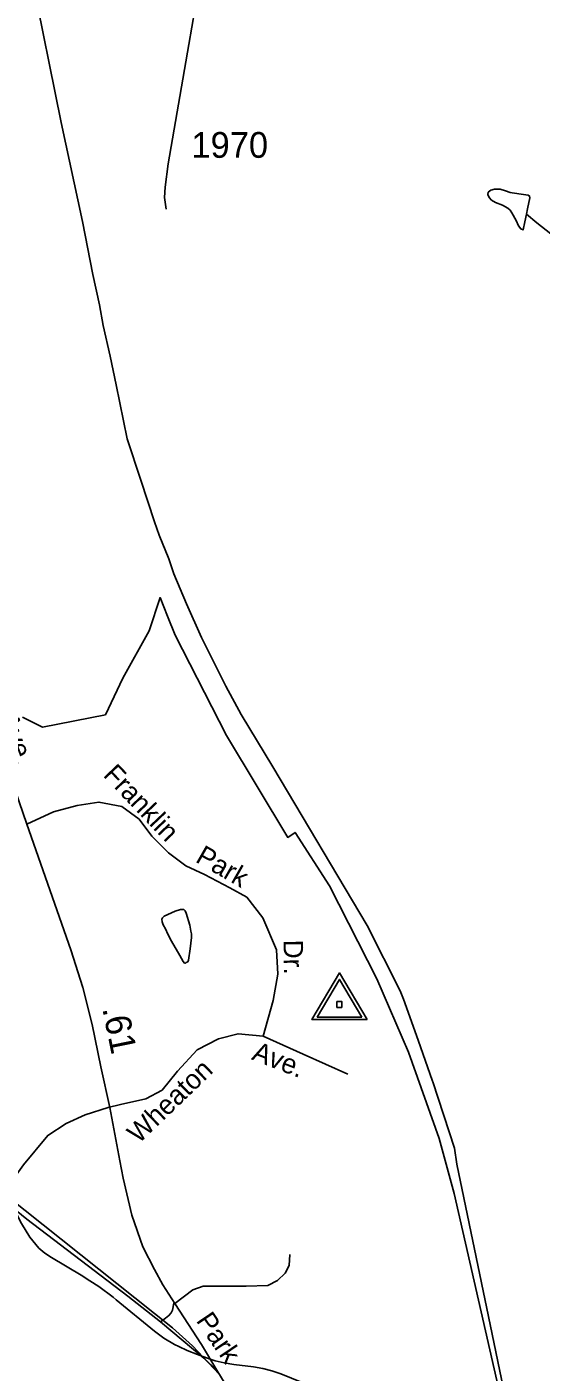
# Model space of a CAD drawing. Extents: x 2126262 to 2293712, y 749403 to 919119.
# Drawn here: x 2151844 to 2154336, y 831196 to 837718 of the extents above; entities that cross this region are included whole.
import ezdxf

# ---------------------------------------------------------------- set-up
doc = ezdxf.new("R2010")
doc.units = 0
for name, color, linetype in [('Exist Boundary Political City Limit New', 7, 'Continuous'), ('Exist Hydrographic Misc Water Feature', 7, 'Continuous'), ('Exist Railroad Mainline', 7, 'Continuous'), ('Exist Road Non-System Type 51', 7, 'Continuous'), ('Exist Road Non-System Type 51 Label', 7, 'Continuous'), ('Exist Road Primary NC Attributed', 7, 'Continuous'), ('Exist Road Primary US Attributed', 7, 'Continuous'), ('Exist Road Primary US Label', 7, 'Continuous'), ('Exist Road Primary US Mileage Hundredths English Label', 7, 'Continuous'), ('Exist Road Primary US Ramp 1 Lane  Attributed', 7, 'Continuous'), ('Exist Road Secondary Type 51 Attributed', 7, 'Continuous'), ('Exist Road Secondary Type 51 Number Label', 7, 'Continuous'), ('Exist Survey Geodetic Marker CELL', 7, 'Continuous'), ('Map Preparation Boundary City Limit Buffer Line', 7, 'Continuous')]:
    doc.layers.add(name, color=color, linetype=linetype)

msp = doc.modelspace()

# ---------------------------------------------------------------- linework, layer by layer
at = {"layer": 'Exist Boundary Political City Limit New'}
for points in [[(2151822.8, 834371.1), (2151919.2, 834322.9), (2152224.5, 834383.1), (2152308.2, 834559.9), (2152437.2, 834789), (2152489, 834950.8), (2152525.5, 834861.3), (2152561.8, 834768.9)], [(2152561.8, 834768.9), (2152810.8, 834282.7), (2153108, 833788.4), (2153144, 833812.6), (2153310, 833552.9), (2153539.5, 833102.3), (2153692.8, 832746.4), (2153843, 832328.9), (2153914.5, 832061.1), (2154336.2, 830213.6)], [(2152776.5, 831185.2), (2152645.8, 831322.7), (2152549, 831410.6), (2151294.2, 832408.8)]]:
    msp.add_lwpolyline(points, dxfattribs=at)
at = {"layer": 'Exist Hydrographic Misc Water Feature'}
for p, q in [((2152261.5, 831558.7), (2152277.3, 831546.8)), ((2152488.1, 831374.8), (2152507.6, 831360.7))]:
    msp.add_line(p, q, dxfattribs=at)
for points in [[(2154264.9, 836809.6), (2154257.1, 836773.5), (2154249.3, 836733.5), (2154237.4, 836739.4), (2154227.4, 836753.3), (2154215.1, 836779.3), (2154194.8, 836817.1), (2154186.8, 836829.1), (2154174.9, 836839), (2154148.8, 836852.9), (2154114.6, 836866.7), (2154096.5, 836878.6), (2154084.6, 836890.6), (2154078.5, 836904.5), (2154080.3, 836916.5), (2154092.2, 836926.5), (2154110.3, 836930.6), (2154138.4, 836930.8), (2154164.4, 836922.9), (2154186.3, 836915.1), (2154196.4, 836913.2), (2154250.3, 836905.5), (2154274.3, 836901.6), (2154280.3, 836897.6), (2154282.5, 836889.7), (2154270.8, 836835.6), (2154264.9, 836809.6)], [(2154264.9, 836809.6), (2154315.1, 836767.8), (2154383.4, 836714.2)], [(2152545.3, 833284.7), (2152585.5, 833214.9), (2152601.7, 833187.1), (2152607.9, 833179.1), (2152611.8, 833179.1), (2152615.9, 833181.1), (2152623.9, 833185.2), (2152627.7, 833193.2), (2152635.5, 833247.2), (2152641.1, 833303.3), (2152641.1, 833321.3), (2152639, 833333.2), (2152632.9, 833363.2), (2152616.5, 833421.1), (2152610.3, 833433), (2152604.4, 833439), (2152598.2, 833439), (2152588.4, 833438.9), (2152562.5, 833430.8), (2152508.6, 833406.5), (2152500.6, 833398.4), (2152498.6, 833392.4), (2152498.8, 833378.4), (2152504.7, 833364.4), (2152515, 833344.5), (2152527.1, 833318.5), (2152545.3, 833284.7)], [(2151793.6, 831962.8), (2151818.2, 831916.2), (2151858.4, 831850.8), (2151901, 831796.9), (2151930.2, 831772.2), (2151962.4, 831751.2), (2152106.3, 831666.2), (2152149, 831638.9)], [(2151793.6, 831962.8), (2151818.2, 831916.2), (2151858.4, 831850.8), (2151901, 831796.9), (2151930.2, 831772.2), (2151962.4, 831751.2), (2152106.3, 831666.2), (2152149, 831638.9)], [(2152149, 831638.9), (2152192.2, 831611.2), (2152261.5, 831558.7)], [(2152149, 831638.9), (2152192.2, 831611.2), (2152261.5, 831558.7)], [(2152277.3, 831546.8), (2152462.5, 831393.5), (2152488.1, 831374.8)], [(2152277.3, 831546.8), (2152462.5, 831393.5), (2152488.1, 831374.8)], [(2152507.6, 831360.7), (2152559.5, 831330.2), (2152580.4, 831320.3)], [(2152507.6, 831360.7), (2152559.5, 831330.2), (2152580.4, 831320.3)], [(2152580.4, 831320.3), (2152621.4, 831300.9), (2152671.2, 831280.5), (2152714.3, 831264.2), (2152737.2, 831257.1)], [(2152580.4, 831320.3), (2152621.4, 831300.9), (2152671.2, 831280.5), (2152714.3, 831264.2), (2152737.2, 831257.1)], [(2152737.2, 831257.1), (2152756.3, 831251.2), (2152799.6, 831241.1), (2152846.3, 831233.2)], [(2152737.2, 831257.1), (2152756.3, 831251.2), (2152799.6, 831241.1), (2152846.3, 831233.2)], [(2152846.3, 831233.2), (2152942.3, 831220.6), (2152987.4, 831213.1), (2153031.3, 831201.9)], [(2152846.3, 831233.2), (2152942.3, 831220.6), (2152987.4, 831213.1), (2153031.3, 831201.9)], [(2153031.3, 831201.9), (2153075.4, 831187.4), (2153177.5, 831144.9), (2153290.3, 831101.4), (2153311, 831088.2)], [(2153031.3, 831201.9), (2153075.4, 831187.4), (2153177.5, 831144.9), (2153290.3, 831101.4), (2153311, 831088.2)]]:
    msp.add_lwpolyline(points, dxfattribs=at)
at = {"layer": 'Exist Railroad Mainline'}
for points in [[(2151866.8, 837966.9), (2152010.1, 837254.7), (2152112.9, 836774.2), (2152163.3, 836518.2), (2152195.8, 836370.2), (2152213.7, 836270.6), (2152248.2, 836121.3), (2152276.2, 835982.2), (2152330.3, 835719.9), (2152395.6, 835520.9), (2152462.6, 835318.5), (2152485.6, 835254), (2152532, 835138.5), (2152556.1, 835065.8), (2152617.3, 834920.2), (2152689.5, 834756.9), (2152807.5, 834520.7), (2152882.8, 834384.8), (2153035.7, 834130.8), (2153493.6, 833360.6), (2153493.6, 833360.6), (2153652.7, 833045.1), (2153669.2, 833003.4), (2153740.5, 832804.5), (2153809.6, 832605.7), (2153811.5, 832603.7)], [(2153811.5, 832603.7), (2153916.7, 832281.3), (2153928.1, 832203.5), (2154081.3, 831464.6), (2155457.3, 824828.4), (2155457.3, 824828.4), (2155482, 824689.4), (2155494.5, 824619), (2155492.8, 824605), (2155538.8, 824353.7), (2155547.3, 824199.9)]]:
    msp.add_lwpolyline(points, dxfattribs=at)
at = {"layer": 'Exist Road Non-System Type 51'}
for points in [[(2151843.9, 833852.8), (2151972.4, 833912.2), (2152086.8, 833942.9), (2152192.8, 833959.7), (2152304.4, 833937.3), (2152388.2, 833875.9), (2152449.5, 833794.9), (2152529.7, 833713.8), (2152613.4, 833649.6), (2152705.4, 833607.7), (2152828.2, 833543.5), (2152909.1, 833498.8), (2152987.3, 833398.3), (2153054, 833243.2), (2153059.6, 833125.9), (2153037.2, 832997.4), (2152989.8, 832824.3)], [(2152989.8, 832824.3), (2152867.1, 832836.1), (2152772.2, 832811), (2152669, 832757.9), (2152574.1, 832654.6), (2152498.8, 832562.4), (2152420.6, 832520.6), (2152297.9, 832492.6), (2152237.8, 832478.4)], [(2152989.8, 832824.3), (2153182.3, 832737.7), (2153400, 832640)], [(2151713.3, 832041.6), (2151827.7, 832200.8), (2151944.9, 832343.2), (2152034.2, 832401.9), (2152126.3, 832443.8), (2152237.8, 832478.4)], [(2152560.2, 831528.3), (2152648.7, 831595), (2152698.9, 831613.1), (2152786.8, 831611.7), (2152906.8, 831611.7), (2153011.4, 831615.9), (2153058.1, 831640.4), (2153095.8, 831675.3), (2153115.3, 831713), (2153118.1, 831766)]]:
    msp.add_lwpolyline(points, dxfattribs=at)
at = {"layer": 'Exist Road Primary NC Attributed'}
for points in [[(2152491.9, 831440.3), (2152332.7, 831563.5), (2151843.7, 831937), (2151713.3, 832041.6), (2151403.6, 832265.4), (2151169.5, 832444.5)], [(2152764.3, 831205.6), (2152700.9, 831263.6), (2152491.9, 831440.3)]]:
    msp.add_lwpolyline(points, dxfattribs=at)
at = {"layer": 'Exist Road Primary US Attributed'}
for points in [[(2152560.2, 831528.3), (2152502.2, 831619.6), (2152461.9, 831693), (2152406.5, 831802.7), (2152353.1, 831955.9), (2152310.4, 832136.5), (2152294.4, 832220.8), (2152246.2, 832478.6), (2152202.5, 832675.8), (2152160.7, 832881.3), (2152114.8, 833060.6), (2152056.7, 833243.1), (2151843.9, 833852.8), (2151732.4, 834177.3)], [(2152764.3, 831205.6), (2152689.7, 831330), (2152560.2, 831528.3)], [(2153889.5, 829414), (2153865.8, 829525.7), (2153831, 829603.9), (2153751.5, 829717.9), (2153600.8, 829902.3), (2153432.1, 830154.3), (2153301.6, 830364.4), (2152899, 830985.6), (2152764.3, 831205.6)]]:
    msp.add_lwpolyline(points, dxfattribs=at)
at = {"layer": 'Exist Road Primary US Ramp 1 Lane  Attributed'}
msp.add_lwpolyline([(2152491.9, 831440.3), (2152516.2, 831457.5), (2152532.1, 831469.6), (2152543, 831482.4), (2152549.4, 831496.4), (2152555.4, 831530.1)], dxfattribs=at)
at = {"layer": 'Exist Road Secondary Type 51 Attributed'}
msp.add_lwpolyline([(2152657.2, 837800.8), (2152629.3, 837633.2), (2152528.5, 837054.4), (2152514.5, 836941.2), (2152511.4, 836890), (2152519.3, 836834)], dxfattribs=at)
at = {"layer": 'Exist Survey Geodetic Marker CELL'}
for points in [[(2153492.8, 832905), (2153358.8, 833131.1), (2153225.3, 832905)], [(2153466.8, 832917.1), (2153251.3, 832917.1), (2153358.8, 833099.3)], [(2153371.1, 832963.7), (2153371.1, 832992), (2153346.9, 832992), (2153346.9, 832963.7)]]:
    msp.add_lwpolyline(points, close=True, dxfattribs=at)
at = {"layer": 'Map Preparation Boundary City Limit Buffer Line'}
for points in [[(2151822.8, 834371.1), (2151919.2, 834322.9), (2152224.5, 834383.1), (2152308.2, 834559.9), (2152437.2, 834789), (2152489, 834950.8), (2152525.5, 834861.3), (2152561.8, 834768.9)], [(2152561.8, 834768.9), (2152810.8, 834282.7), (2153108, 833788.4), (2153144, 833812.6), (2153310, 833552.9), (2153539.5, 833102.3), (2153692.8, 832746.4), (2153843, 832328.9), (2153914.5, 832061.1), (2154336.2, 830213.6)], [(2152776.5, 831185.2), (2152645.8, 831322.7), (2152549, 831410.6), (2151294.2, 832408.8)]]:
    msp.add_lwpolyline(points, dxfattribs=at)

# ---------------------------------------------------------------- texts
at = {"layer": 'Exist Road Non-System Type 51 Label'}
for s, rotation, p in [('Franklin', 313.51251, (2152209.5, 834087.8)), ('Park', 330.13632, (2152655.9, 833672.1)), ('Dr.', 270.72503, (2153087.5, 833291.6)), ('Ave.', 338.83148, (2152928.8, 832712.8)), ('Wheaton', 43.8979, (2152385.9, 832299.8))]:
    msp.add_text(s, height=95, rotation=rotation, dxfattribs=at).set_placement(p)
at = {"layer": 'Exist Road Primary US Label'}
for s, rotation, p in [('Ave.', 290.17007, (2151705.6, 834369.6)), ('Park', 304.10423, (2152661.2, 831445.6))]:
    msp.add_text(s, height=95, rotation=rotation, dxfattribs=at).set_placement(p)
at = {"layer": 'Exist Road Primary US Mileage Hundredths English Label'}
msp.add_text('.61', height=125, rotation=281.49801, dxfattribs=at).set_placement((2152208.8, 832958.7))
at = {"layer": 'Exist Road Secondary Type 51 Number Label'}
msp.add_text('1970', height=125, dxfattribs=at).set_placement((2152641.1, 837083.1))

doc.saveas('drawing.dxf')
